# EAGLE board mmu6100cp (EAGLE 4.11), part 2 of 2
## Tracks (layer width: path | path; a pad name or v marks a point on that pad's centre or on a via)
00\  (via drill 0.61)
  Top 0.254: v64.14,104.78 v64.14,109.22
  Bottom 0.254: v64.14,104.78 87,104.78 88.9,106.68 IC12.8 | v64.14,109.22 IC16.9
00FLT\  (via drill 0.61)
  Top 0.254: v80.01,22.86 79.38,23.5 v79.38,30.48 | v69.22,30.48 67.31,32.38 v67.31,34.29 | v18.41,36.2 18.41,73.03 15.88,75.56 v15.88,87.63 | v60.96,92.08 IC16.8
  Bottom 0.254: v69.22,30.48 v79.38,30.48 | v67.31,34.29 66.04,35.56 61.59,35.56 60.96,34.92 53.34,34.92 52.7,35.56 49.53,35.56 48.9,36.2 v18.41,36.2 | v15.88,87.63 20.32,92.08 v60.96,92.08 | v80.01,22.86 IC13.3
2X\  (via drill 0.61)
  Top 0.254: v62.87,104.14 62.87,114.94 IC16.12 | v93.98,102.87 94.61,103.5 v94.61,107.95
  Bottom 0.254: v62.87,104.14 63.5,103.5 71.75,103.5 72.39,104.14 86.36,104.14 87.63,102.87 v93.98,102.87 | v94.61,107.95 95.89,109.22 IC14.6
2XFLT\  (via drill 0.61)
  Top 0.254: 124.46,6.35 101.6,6.35 97.16,10.79 97.16,13.97 93.34,17.78 93.34,19.05 90.17,19.05 88.9,17.78 IC13.5 | 124.46,6.35 124.46,22.23 123.83,22.86 v123.83,24.13 | v56.52,104.14 v56.52,111.76 | v38.1,103.5 35.56,106.05 v35.56,114.3 | v127,6.35 125.73,5.08 124.46,5.08 124.46,6.35
  Bottom 0.254: v123.83,24.13 125.09,25.4 IC18.2 | v56.52,111.76 57.15,111.76 59.69,114.3 IC16.11 | v56.52,104.14 55.88,103.5 v38.1,103.5 | v35.56,114.3 34.92,113.67 8.89,113.67 1.27,106.05 1.27,15.24 2.54,15.24 12.7,5.08 35.56,5.08 35.56,9.53 45.09,9.53 48.26,6.35 55.88,6.35 57.15,7.62 59.05,5.71 126.36,5.71 v127,6.35
AND\
  Top 0.254: IC9.15 PAD1.1
BADHLT\  (via drill 0.61)
  Top 0.254: v132.08,21.59 132.72,22.23 132.72,34.92 127,40.64 127,78.11 124.46,80.64 v124.46,88.9
  Bottom 0.254: v132.08,21.59 134.62,21.59 135.89,20.32 IC18.11 | v124.46,88.9 123.19,90.17 117.47,90.17 116.2,91.44 IC19.1
BFLD0  (via drill 0.61)
  Top 0.254: v73.03,93.98 73.03,75.56 v69.22,71.75 | v64.14,68.58 63.5,67.94 v63.5,49.53
  Bottom 0.254: IC24.7 95.25,48.26 92.71,50.8 IC4.15 90.17,50.8 88.9,52.07 74.93,52.07 72.39,49.53 v63.5,49.53 | v69.22,71.75 66.04,68.58 v64.14,68.58 | v73.03,93.98 IC23.2
BFLD1  (via drill 0.61)
  Top 0.254: IC4.12 93.34,45.09 v93.34,54.61 93.34,60.33 v93.98,60.96 | v70.48,74.93 70.48,87 IC23.4 | v85.72,74.93 87,73.66 v87,62.23
  Bottom 0.254: v93.34,54.61 94.61,55.88 IC24.4 | v85.72,74.93 v70.48,74.93 | v87,62.23 92.71,62.23 v93.98,60.96
BFLD2  (via drill 0.61)
  Top 0.254: v88.27,43.81 v88.27,55.88 88.9,56.52 88.9,62.87 88.27,63.5 88.27,82.55 v85.72,85.09
  Bottom 0.254: v88.27,43.81 85.72,43.81 85.09,43.18 IC4.9 | v88.27,55.88 89.53,57.15 93.34,57.15 94.61,58.42 IC24.3 | v85.72,85.09 71.12,85.09 69.85,83.82 IC23.6
C0\  (via drill 0.61)
  Top 0.254: v26.04,66.04 25.4,66.67 RN1.8 | v59.69,67.31 59.69,60.33 58.42,59.05 SV1.24
  Bottom 0.254: v26.04,66.04 CPU.32 38.73,66.67 43.81,66.67 44.45,67.31 v59.69,67.31
C1\  (via drill 0.61)
  Top 0.254: v57.15,69.85 57.15,62.87 58.42,61.59 SV1.22 | v27.3,69.22 27.3,94.61 27.94,95.25 RN1.9
  Bottom 0.254: v57.15,69.85 40.64,69.85 39.37,68.58 CPU.33 27.94,68.58 v27.3,69.22
C2\  (via drill 0.61)
  Top 0.254: v30.48,71.12 RN1.10 | v43.18,64.77 42.55,65.41 v42.55,71.12
  Bottom 0.254: v30.48,71.12 CPU.34 v42.55,71.12 | v43.18,64.77 56.52,64.77 57.78,63.5 SV1.20
CLRST\  (via drill 0.61)
  Top 0.254: v93.98,96.52 93.34,95.89 v93.34,64.77 | v121.28,95.25 121.28,97.79 120.02,99.06 120.02,113.03 123.19,113.03 127,116.84 IC15.3
  Bottom 0.254: IC4.1 85.09,63.5 86.36,64.77 v93.34,64.77 96.52,64.77 97.79,63.5 IC24.1 | v93.98,96.52 IC5.1 101.6,96.52 102.87,95.25 107.95,95.25 108.58,94.61 112.39,94.61 113.67,95.89 120.65,95.89 v121.28,95.25
CPREQ\  (via drill 0.61)
  Top 0.254: CPU.5 20.32,78.74 RN1.6 13.97,102.87 1.27,102.87 1.27,13.97 3.81,11.43 v12.7,11.43 | IC13.4 81.92,22.23 81.92,23.5 IC13.2 | IC13.6 89.53,15.24 89.53,14.61 IC13.8 90.17,12.7 90.17,6.99 67.94,6.99 v63.5,11.43 63.5,38.73 59.05,43.18 SV1.36 | v80.01,17.78 v80.01,20.32
  Bottom 0.254: v80.01,17.78 82.55,15.24 IC13.6 | v80.01,20.32 IC13.4 | v12.7,11.43 13.34,10.79 27.94,10.79 28.57,11.43 v63.5,11.43
CPSEL  (via drill 0.61)
  Top 0.254: IC29.9 74.3,111.12 74.3,114.94 IC29.12 | v136.53,72.39 136.53,75.56 IC22.8 | v83.82,71.12 81.28,73.66 v81.28,109.22 | v102.23,118.11 v102.23,114.3
  Bottom 0.254: v136.53,72.39 134.62,70.48 84.45,70.48 v83.82,71.12 | v81.28,109.22 IC29.9 | v102.23,118.11 78.74,118.11 77.47,116.84 IC29.12 | v102.23,114.3 IC14.11
CPSEL\  (via drill 0.61)
  Top 0.254: v3.81,64.14 2.54,62.87 v2.54,13.97 | v52.7,3.81 54.61,1.91 56.52,1.91 56.52,5.71 55.88,6.35 55.88,19.68 v56.52,20.32 | v95.89,20.32 95.89,34.92 95.25,35.56 v95.25,36.2 | v122.56,36.2 124.46,38.1 v124.46,62.23 | v131.44,62.23 132.08,62.87 v132.08,78.74
  Bottom 0.254: v3.81,64.14 5.08,64.14 20.95,80.01 24.13,80.01 25.4,81.28 CPU.38 | v2.54,13.97 12.06,4.45 44.45,4.45 45.09,3.81 v52.7,3.81 | v56.52,20.32 58.42,20.32 59.69,19.05 94.61,19.05 v95.89,20.32 | v95.25,36.2 95.89,36.83 98.42,36.83 99.69,35.56 119.38,35.56 120.02,36.2 v122.56,36.2 | v124.46,62.23 v131.44,62.23 | v132.08,78.74 IC22.9
CPUDEVSEL\  (via drill 0.61)
  Top 0.254: IC16.13 59.05,117.47 59.05,113.67 IC16.10 59.05,109.86 v59.05,98.42 | CPU.30 40.01,62.87 40.01,120.02 IC11.1 | v127.64,35.56 127.64,22.23 IC18.4 | v156.84,39.37 157.48,40.01 157.48,64.77 158.75,66.04 158.75,93.98 146.69,106.05 | 146.69,106.05 v140.34,112.39 | v117.47,118.11 116.2,119.38 116.2,120.02 115.57,120.65 107.31,120.65 107.31,120.02 IC14.13 | v108.58,98.42 112.39,94.61 113.67,94.61 v113.67,100.97 | v141.6,100.97 146.69,106.05
  Bottom 0.254: IC16.13 55.88,119.38 54.61,120.65 42.55,120.65 41.27,121.92 IC11.1 | v127.64,35.56 128.91,36.83 145.41,36.83 147.96,39.37 v156.84,39.37 | v140.34,112.39 137.16,115.57 127,115.57 124.46,118.11 v117.47,118.11 | v59.05,98.42 v108.58,98.42 | v113.67,100.97 v141.6,100.97
CPUINTREQ\  (via drill 0.61)
  Top 0.254: v12.7,70.48 RN1.3
  Bottom 0.254: v12.7,70.48 19.68,70.48 21.59,68.58 CPU.8 | IC16.3 52.07,116.84 51.44,116.2 47.62,116.2 46.99,115.57 41.91,115.57 39.37,113.03 18.41,113.03 5.08,99.69 5.08,98.42 10.79,98.42 RN1.3
CPUSWSEL\  (via drill 0.61)
  Top 0.254: v36.83,100.97 36.83,95.25 36.2,94.61 36.2,65.41 CPU.31 | v43.18,102.23 v45.72,99.69 | v82.55,102.23 81.92,102.87 81.92,107.31 82.55,107.95 85.09,107.95 86.36,109.22 86.36,114.3 87.63,115.57 89.53,115.57 89.53,113.67 90.17,113.03 93.34,113.03 93.34,111.76 94.61,110.49 95.89,110.49 | 95.89,110.49 95.89,116.2 IC14.2 | v140.34,107.31 140.34,100.97 142.88,98.42 142.88,17.78 IC18.10 | 95.89,110.49 v95.89,107.95
  Bottom 0.254: v36.83,100.97 38.1,102.23 v43.18,102.23 | v45.72,99.69 46.35,100.33 56.52,100.33 57.15,100.97 67.94,100.97 69.22,102.23 73.03,102.23 73.66,102.87 81.92,102.87 v82.55,102.23 | v140.34,107.31 137.16,110.49 113.03,110.49 110.49,107.95 v95.89,107.95
DATAF  (via drill 0.61)
  Top 0.254: v48.9,86.36 49.53,87 49.53,95.89 | 49.53,95.89 49.53,110.49 IC16.4 | v141.6,60.96 140.97,61.59 v140.97,97.16 | 49.53,95.89 v48.9,95.89
  Bottom 0.254: CPU.40 v48.9,86.36 | v140.97,97.16 108.58,97.16 107.95,97.79 59.69,97.79 57.78,95.89 v48.9,95.89 | v141.6,60.96 IC17.19
DCA\
  Top 0.254: IC9.12 PAD4.1
DEVSEL\  (via drill 0.61)
  Top 0.254: v102.87,15.24 101.6,13.97 v101.6,7.62 | v59.05,8.89 59.05,18.41 59.69,19.05 62.87,19.05 62.87,33.02 v59.69,36.2 | v16.51,40.64 13.97,43.18 13.97,85.72 13.34,86.36 13.34,87 v15.88,89.53 | v74.3,92.71 73.66,92.08 v73.66,73.66
  Bottom 0.254: v102.87,15.24 104.14,16.51 127,16.51 128.27,15.24 IC18.6 | v101.6,7.62 100.97,6.99 64.14,6.99 62.23,8.89 v59.05,8.89 | v59.69,36.2 50.16,36.2 49.53,36.83 20.32,36.83 v16.51,40.64 | v15.88,89.53 19.05,92.71 60.33,92.71 60.96,93.34 66.67,93.34 67.31,92.71 v74.3,92.71 | v73.66,73.66 67.31,67.31 60.96,67.31 59.69,68.58 SV1.16
DFLD0  (via drill 0.61)
  Top 0.254: v85.09,38.73 85.72,39.37 85.72,48.9 IC4.6
  Bottom 0.254: v85.09,38.73 85.72,38.1 90.17,38.1 91.44,36.83 92.71,36.83 93.34,37.47 99.06,37.47 100.33,36.2 118.75,36.2 120.02,37.47 135.25,37.47 137.79,40.01 IC17.11
DFLD1
  Bottom 0.254: IC4.5 85.09,53.34 85.72,52.7 89.53,52.7 90.17,52.07 95.25,52.07 97.79,49.53 132.08,49.53 135.89,45.72 IC17.13
DFLD2  (via drill 0.61)
  Top 0.254: v85.72,65.41 85.72,62.87 IC4.2 | v123.19,64.77 124.46,66.04 125.73,66.04 v125.73,53.98
  Bottom 0.254: v85.72,65.41 86.36,66.04 100.33,66.04 102.23,64.14 104.78,64.14 105.41,64.77 v123.19,64.77 | v125.73,53.98 127.64,52.07 134.62,52.07 135.89,50.8 IC17.15
DMAGNT
  Bottom 0.254: CPU.3 24.13,81.28 24.77,81.92 36.2,81.92 36.83,82.55 39.37,82.55 40.64,81.28 SV1.5
DMAREQ\
  Top 0.254: CPU.4 20.95,80.64 20.95,93.34 22.86,95.25 RN1.7
  Bottom 0.254: SV1.7 40.64,78.74 39.37,77.47 25.4,77.47 24.13,78.74 CPU.4
DX0  (via drill 0.61)
  Top 0.254: IC3.7 20.95,17.14 20.95,46.35 CPU.16 | v57.15,77.47 57.15,73.03 55.88,71.75 SV1.13 | v100.97,71.75 100.97,76.83 IC5.8 | v26.67,49.53 27.94,50.8 27.94,66.67 28.57,67.31 v28.57,72.39
  Bottom 0.254: 180.34,59.69 187.96,59.69 189.23,58.42 IC21.15 | 180.34,59.69 173.99,59.69 173.35,59.05 169.54,59.05 168.91,58.42 IC28.15 | SV1.13 RN2.2 44.45,71.12 43.18,72.39 v28.57,72.39 | IC5.8 96.52,78.74 95.25,80.01 90.17,80.01 88.9,78.74 IC7.8 82.55,78.74 81.28,77.47 v57.15,77.47 | 180.34,59.69 180.34,72.39 156.21,72.39 153.67,74.93 137.16,74.93 133.35,71.12 101.6,71.12 v100.97,71.75 | v26.67,49.53 25.4,49.53 24.13,48.26 CPU.16
DX1  (via drill 0.61)
  Top 0.254: 24.77,43.81 24.77,19.68 IC3.6 | 24.77,43.81 CPU.17 | v27.3,67.31 27.3,51.44 24.77,48.9 24.77,43.81 | v53.98,85.09 53.98,71.12 55.88,69.22 SV1.15 | v133.35,72.39 v133.35,62.23 | v108.58,77.47 v108.58,72.39 | v97.16,77.47 97.16,79.38 IC5.7
  Bottom 0.254: IC21.13 173.99,60.96 172.72,59.69 166.37,59.69 165.74,60.33 154.31,60.33 153.67,60.96 IC28.13 151.13,60.96 150.5,61.59 142.24,61.59 141.6,62.23 v133.35,62.23 | IC5.7 97.16,81.28 95.89,82.55 86.36,82.55 85.09,81.28 IC7.7 82.55,81.28 81.28,82.55 61.59,82.55 59.05,85.09 v53.98,85.09 | SV1.15 RN2.3 44.45,68.58 43.18,67.31 v27.3,67.31 | v108.58,72.39 v133.35,72.39 | v97.16,77.47 v108.58,77.47
DX2  (via drill 0.61)
  Top 0.254: v27.3,43.18 27.3,27.3 v26.67,26.67 26.67,9.53 v33.02,3.17 | v34.92,64.77 31.75,61.59 v31.75,43.18 | v80.01,88.9 80.64,88.27 80.64,73.66 v73.03,66.04 | v158.75,63.5 159.38,62.87 159.38,24.13 160.66,22.86 160.66,17.78 160.02,17.14 160.02,3.17 v159.38,2.54
  Bottom 0.254: IC28.12 v158.75,63.5 165.1,63.5 166.37,64.77 172.72,64.77 173.99,63.5 IC21.12 | IC5.4 95.89,88.9 94.61,90.17 86.36,90.17 85.09,88.9 IC7.4 v80.01,88.9 | v26.67,26.67 25.4,26.67 24.13,25.4 IC3.3 | CPU.18 v27.3,43.18 v31.75,43.18 | v34.92,64.77 39.37,64.77 40.64,66.04 RN2.4 SV1.17 56.52,66.04 57.78,64.77 71.75,64.77 v73.03,66.04 | v159.38,2.54 158.75,1.91 34.29,1.91 v33.02,3.17
DX3  (via drill 0.61)
  Top 0.254: v26.04,39.37 v26.04,27.94 25.4,27.3 25.4,9.53 v31.75,3.17 | v52.07,90.17 52.7,89.53 52.7,67.31 55.88,64.14 SV1.19 | v94.61,88.9 v94.61,91.44 | v45.72,38.73 47.62,40.64 47.62,51.44 46.99,52.07 43.81,52.07 43.81,61.59 RN2.5 | v159.38,64.77 160.02,64.14 160.02,24.77 161.29,23.5 161.29,17.14 160.66,16.51 v160.66,2.54
  Bottom 0.254: 159.38,67.31 172.72,67.31 173.99,66.04 IC21.11 | 159.38,67.31 154.94,67.31 153.67,66.04 IC28.11 | v26.04,27.94 IC3.2 | CPU.19 24.77,40.64 v26.04,39.37 45.09,39.37 v45.72,38.73 | RN2.5 SV1.19 | v52.07,90.17 77.47,90.17 | 77.47,90.17 81.28,90.17 82.55,91.44 IC7.3 | v94.61,88.9 93.34,87.63 80.01,87.63 77.47,90.17 | v94.61,91.44 IC5.3 | v159.38,64.77 159.38,67.31 | v160.66,2.54 159.38,1.27 33.66,1.27 v31.75,3.17
DX4  (via drill 0.61)
  Top 0.254: v31.75,38.1 33.02,39.37 v33.02,53.34 | v109.86,101.6 109.86,114.94 IC2.2 | v105.41,101.6 104.14,100.33 104.14,60.33 v104.78,59.69 | v164.47,58.42 164.47,26.04 IC27.19 | v72.39,62.23 73.03,61.59 v73.03,58.42
  Bottom 0.254: v33.02,53.34 36.83,57.15 40.64,57.15 44.45,60.96 RN2.6 SV1.21 56.52,60.96 57.78,62.23 v72.39,62.23 | CPU.20 v31.75,38.1 | IC27.19 168.91,22.86 170.18,24.13 187.96,24.13 189.23,22.86 IC20.19 | v105.41,101.6 v109.86,101.6 | v164.47,58.42 163.19,59.69 v104.78,59.69 93.98,59.69 92.71,58.42 IC4.18 89.53,58.42 88.27,57.15 82.55,57.15 81.92,57.78 78.11,57.78 77.47,58.42 IC6.18 v73.03,58.42
DX5  (via drill 0.61)
  Top 0.254: v41.91,38.1 45.09,41.27 45.09,42.55 RN2.13 | v116.2,90.17 116.2,114.94 IC2.3 | v102.23,58.42 v102.23,65.41 v102.23,90.17 | v162.56,62.23 162.56,20.32 IC27.18 | v60.33,55.88 59.69,55.24 59.69,44.45 57.78,44.45 56.52,43.18 SV1.35 | v71.75,57.15 v73.03,55.88
  Bottom 0.254: CPU.21 v41.91,38.1 | RN2.13 SV1.35 | IC27.18 168.91,20.32 169.54,20.95 173.35,20.95 173.99,21.59 187.96,21.59 189.23,20.32 IC20.18 | v102.23,90.17 v116.2,90.17 | v102.23,58.42 100.97,57.15 94.61,57.15 93.34,55.88 IC4.17 90.17,55.88 88.9,54.61 78.74,54.61 77.47,55.88 IC6.17 v73.03,55.88 | v162.56,62.23 142.88,62.23 139.06,66.04 102.87,66.04 v102.23,65.41 | v60.33,55.88 61.59,57.15 v71.75,57.15
DX6  (via drill 0.61)
  Top 0.254: v62.23,44.45 60.33,44.45 v60.33,43.81 | IC6.14 74.93,48.26 73.03,46.35 v73.03,45.72 74.3,44.45 v74.3,39.37 | v165.1,105.41 187.32,83.19 187.32,20.95 IC20.17 | v82.55,38.1 82.55,29.21 81.28,27.94 v81.28,17.78 | v93.34,16.51 96.52,13.34 96.52,10.16 104.14,2.54 146.05,2.54 v146.05,17.78
  Bottom 0.254: IC6.14 77.47,48.26 78.11,47.62 81.92,47.62 82.55,46.99 88.9,46.99 90.17,48.26 IC4.14 | 57.15,44.45 57.15,45.09 55.88,45.09 SV1.33 RN2.12 | 57.15,44.45 57.15,42.55 56.52,41.91 55.24,41.91 53.98,40.64 CPU.22 | v73.03,45.72 71.75,44.45 v62.23,44.45 | v60.33,43.81 59.69,44.45 57.15,44.45 | v165.1,105.41 119.38,105.41 115.57,109.22 IC2.6 | IC20.17 189.23,17.78 187.96,19.05 173.99,19.05 173.35,18.41 169.54,18.41 168.91,17.78 IC27.17 166.37,17.78 165.1,19.05 147.32,19.05 v146.05,17.78 | v74.3,39.37 75.56,38.1 v82.55,38.1 | v81.28,17.78 82.55,16.51 v93.34,16.51
DX7  (via drill 0.61)
  Top 0.254: v41.91,43.18 43.81,45.09 43.81,46.35 RN2.11 | v102.23,106.05 101.6,105.41 101.6,92.08 103.5,90.17 v103.5,48.26 | v196.85,90.17 196.85,21.59 IC20.16 | v112.39,101.6 112.39,104.78 IC2.7 | v57.15,52.07 57.15,50.16 55.88,48.9 SV1.31 | v73.03,52.07 74.3,50.8 74.3,50.16 74.93,49.53 78.11,49.53 78.11,47.62 IC6.13
  Bottom 0.254: v41.91,43.18 CPU.23 | SV1.31 RN2.11 | IC27.16 168.91,15.24 169.54,15.88 173.35,15.88 173.99,16.51 187.96,16.51 189.23,15.24 IC20.16 | IC6.13 77.47,45.72 78.74,44.45 87.63,44.45 88.9,45.72 IC4.13 92.71,45.72 93.98,46.99 102.23,46.99 v103.5,48.26 | v102.23,106.05 102.87,105.41 111.76,105.41 113.03,106.68 IC2.7 | v196.85,90.17 185.42,101.6 142.24,101.6 141.6,102.23 113.03,102.23 v112.39,101.6 | v73.03,52.07 v57.15,52.07
DX8  (via drill 0.61)
  Top 0.254: v34.29,45.72 34.92,45.09 34.92,18.41 IC1.7 | v41.91,48.26 44.45,50.8 RN2.10 | v118.11,12.06 117.47,12.7 v117.47,13.97 | v109.22,13.97 104.14,13.97 v104.14,22.86 | v86.36,22.86 85.09,24.13 85.72,24.77 85.72,36.2 81.92,40.01 81.92,43.81 IC4.8
  Bottom 0.254: 179.07,12.7 177.8,12.7 176.53,11.43 170.18,11.43 168.91,12.7 IC27.15 | 179.07,12.7 IC20.15 | IC4.8 82.55,45.72 81.28,46.99 71.12,46.99 69.85,45.72 IC6.8 60.96,45.72 59.69,46.99 40.64,46.99 | RN2.10 SV1.29 | v34.29,45.72 CPU.24 39.37,45.72 40.64,46.99 | 40.64,46.99 v41.91,48.26 | 179.07,12.7 179.07,9.53 120.65,9.53 v118.11,12.06 | v109.22,13.97 v117.47,13.97 | v104.14,22.86 103.5,23.5 100.97,23.5 100.33,24.13 87.63,24.13 v86.36,22.86
DX9  (via drill 0.61)
  Top 0.254: v177.16,10.79 177.16,13.34 IC20.13 | IC27.13 154.31,13.34 v154.31,11.43 v147.32,4.45 | v34.92,46.99 35.56,46.35 35.56,20.32 IC1.6 40.01,15.88 40.01,12.06 v46.99,5.08
  Bottom 0.254: v154.31,11.43 154.94,10.79 v177.16,10.79 | IC4.7 82.55,48.26 81.28,49.53 74.93,49.53 74.3,48.9 70.48,48.9 69.85,48.26 IC6.7 60.33,48.26 59.05,49.53 40.64,49.53 | v34.92,46.99 36.2,48.26 CPU.25 39.37,48.26 40.64,49.53 | 40.64,49.53 44.45,53.34 RN2.9 SV1.27 | v147.32,4.45 146.69,5.08 131.44,5.08 130.18,3.81 57.15,3.81 55.88,5.08 v46.99,5.08
DX10  (via drill 0.61)
  Top 0.254: IC1.3 36.2,27.3 36.2,51.44 CPU.27 | v146.05,26.67 146.05,24.13 IC27.12 | v80.01,31.75 79.38,32.38 79.38,59.69 80.64,60.96 81.92,60.96 81.92,57.78 IC4.4
  Bottom 0.254: IC27.12 165.1,17.78 166.37,16.51 172.72,16.51 173.99,17.78 IC20.12 | IC4.4 82.55,55.88 81.28,57.15 73.03,57.15 71.75,55.88 IC6.4 67.31,55.88 66.67,55.24 60.96,55.24 60.33,54.61 57.78,54.61 56.52,55.88 SV1.25 RN2.8 45.09,55.24 41.27,55.24 39.37,53.34 CPU.27 | v146.05,26.67 142.24,30.48 82.55,30.48 81.28,31.75 v80.01,31.75
DX11  (via drill 0.61)
  Top 0.254: IC1.2 40.01,29.84 40.01,53.98 CPU.28 | v81.28,30.48 81.28,53.34 82.55,54.61 85.72,54.61 85.72,56.52 IC4.3
  Bottom 0.254: CPU.28 41.91,55.88 44.45,58.42 RN2.7 SV1.23 56.52,58.42 57.78,59.69 66.04,59.69 | IC20.11 173.99,20.32 172.72,19.05 166.37,19.05 165.74,19.68 154.31,19.68 153.67,20.32 IC27.11 151.13,20.32 141.6,29.84 81.92,29.84 v81.28,30.48 | 66.04,59.69 67.31,58.42 IC6.3 | 66.04,59.69 81.28,59.69 82.55,58.42 IC4.3
EMA0  (via drill 0.61)
  Top 0.254: IC28.26 169.54,84.45 169.54,42.55 IC27.26 | v71.12,91.44 70.48,92.08 v70.48,118.11 | v20.32,102.23 v36.2,118.11 | v12.7,101.6 8.89,97.79 8.89,64.14 8.26,63.5 8.26,62.23 9.53,60.96 v9.53,48.26 | v53.34,41.91 54.61,43.18 54.61,46.35 55.24,46.99 58.42,46.99 SV1.34
  Bottom 0.254: IC28.26 168.91,86.36 169.54,85.72 173.35,85.72 173.99,85.09 176.53,85.09 177.16,85.72 177.16,90.81 175.9,90.81 IC21.1 | IC27.26 168.91,40.64 169.54,40.01 173.35,40.01 173.99,39.37 176.53,39.37 177.16,40.01 177.16,45.09 175.9,45.09 IC20.1 173.99,45.72 172.72,44.45 156.21,44.45 148.59,52.07 RN3.2 143.51,52.07 139.06,47.62 | 139.06,47.62 139.06,45.09 138.43,44.45 132.08,44.45 130.81,43.18 IC17.9 128.27,43.18 127,41.91 63.5,41.91 59.69,45.72 SV1.34 | 139.06,47.62 137.79,47.62 IC17.14 | v36.2,118.11 v70.48,118.11 | v20.32,102.23 19.68,101.6 v12.7,101.6 | v9.53,48.26 15.88,41.91 v53.34,41.91 | v71.12,91.44 IC23.18
EMA1  (via drill 0.61)
  Top 0.254: v65.41,85.09 66.04,84.45 66.04,47.62 v65.41,46.99 64.77,46.35 64.77,12.7 v68.58,8.89 | 192.41,54.61 192.41,84.45 IC21.26 | 192.41,54.61 192.41,42.55 IC20.26 | 131.44,50.16 133.35,52.07 v133.35,53.34 | 131.44,50.16 IC17.7 | IC27.2 154.31,45.09 v154.31,54.61 154.31,87 IC28.2 | 192.41,54.61 v189.87,54.61 | v132.72,8.26 133.99,9.53 133.99,40.64 131.44,43.18 131.44,50.16
  Bottom 0.254: v65.41,85.09 69.85,85.09 70.48,85.72 74.3,85.72 74.93,86.36 IC23.16 | v65.41,46.99 64.77,47.62 58.42,47.62 SV1.32 | v133.35,53.34 IC17.16 142.24,53.34 143.51,54.61 RN3.3 v154.31,54.61 v189.87,54.61 | v68.58,8.89 69.22,9.53 114.94,9.53 116.2,8.26 v132.72,8.26
EMA2  (via drill 0.61)
  Top 0.254: v64.77,80.01 65.41,79.38 65.41,51.44 v64.77,50.8 | 170.18,35.56 170.81,36.2 v170.81,43.18 v170.81,78.74 | 170.18,35.56 IC27.23 | 173.35,56.52 173.35,45.09 IC20.2 | 173.35,56.52 173.35,87 IC21.2 | 173.35,56.52 v173.99,56.52 | v60.96,50.8 61.59,51.44 61.59,55.88 60.33,57.15 52.07,57.15 52.07,34.29 55.24,31.11 v55.24,3.17 | v165.1,7.62 170.18,12.7 170.18,35.56
  Bottom 0.254: v64.77,80.01 69.85,80.01 71.12,81.28 IC23.14 | v64.77,50.8 v60.96,50.8 SV1.30 | IC17.5 130.81,53.34 135.89,58.42 IC17.18 142.24,58.42 143.51,57.15 RN3.4 146.05,57.15 146.69,56.52 v173.99,56.52 | IC20.2 v170.81,43.18 | v170.81,78.74 IC28.23 | v55.24,3.17 55.88,2.54 158.12,2.54 163.19,7.62 v165.1,7.62
ERROR\  (via drill 0.61)
  Top 0.254: v84.45,31.75 84.45,28.57 IC13.1 | v106.05,31.75 109.86,27.94 v109.86,22.86
  Bottom 0.254: v84.45,31.75 85.09,31.11 105.41,31.11 v106.05,31.75 | v109.86,22.86 IC10.3
GND  (via drill 0.61)
  Top 0.254: IC27.1 151.76,46.35 151.76,57.78 IC28.14 150.5,60.33 150.5,89.53 IC28.1 | IC27.14 144.78,20.32 RN3.1 | IC17.10 127.64,42.55 127.64,43.81 IC17.8 127.64,47.62 127.64,78.11 | 125.09,102.87 126.36,104.14 126.36,104.78 IC15.7 | 125.09,102.87 123.83,102.87 123.83,109.86 IC2.12 | IC7.13 90.81,79.38 90.81,80.64 IC7.14 89.53,83.19 89.53,87 IC7.17 90.81,89.53 90.81,90.81 IC7.18 | 125.09,102.87 126.36,101.6 126.36,81.28 127.64,80.01 127.64,78.11 | 127.64,78.11 IC22.7 | IC9.8 9.53,14.61 9.53,18.41 IC9.5 6.99,20.95 6.99,22.23 IC9.4 3.81,22.86 v3.81,53.34 | QG2.7 7.62,52.7 | v28.57,10.16 28.57,18.41 IC3.12 | IC12.7 IC7.1 81.92,94.61 81.92,75.56 IC7.10 | IC13.7 82.55,12.7 82.55,8.26 74.3,8.26 69.85,12.7 IC8.7 70.48,14.61 70.48,34.92 69.22,36.2 69.22,40.01 IC6.10 66.67,42.55 66.67,61.59 IC6.1 67.94,64.14 67.94,73.03 IC23.10 66.67,75.56 66.67,76.83 | 66.67,76.83 IC23.8 | 66.67,85.09 v65.41,86.36 | 66.67,85.09 66.67,76.83 | 66.67,85.09 66.67,104.78 IC29.7 | v41.91,53.34 41.27,53.98 41.27,72.39 v42.55,73.66
  Bottom 0.254: IC18.7 130.81,12.7 132.08,11.43 149.86,11.43 151.13,12.7 IC27.14 156.21,12.7 157.48,13.97 172.72,13.97 173.99,12.7 IC20.14 | IC17.17 173.35,55.88 173.99,55.24 175.26,56.52 IC21.14 173.99,58.42 172.72,57.15 154.94,57.15 153.67,58.42 IC28.14 | IC28.27 166.37,88.9 163.83,91.44 IC28.1 | IC27.27 166.37,43.18 165.74,43.81 155.57,43.81 153.67,45.72 IC27.1 149.86,45.72 146.05,49.53 RN3.1 144.15,48.9 144.15,41.91 132.72,41.91 131.44,40.64 IC17.10 128.27,40.64 127,39.37 101.6,39.37 100.33,40.64 IC24.10 97.79,40.64 96.52,39.37 86.36,39.37 85.09,40.64 IC4.10 | IC25.7 115.57,45.72 116.84,46.99 127,46.99 128.27,45.72 IC17.8 | IC7.10 85.09,73.66 86.36,72.39 94.61,72.39 95.89,73.66 IC5.10 | 111.76,74.93 113.03,76.2 IC19.7 | 111.76,74.93 101.6,74.93 100.33,73.66 IC5.10 | 111.76,74.93 127,74.93 128.27,76.2 IC22.7 | IC7.13 92.71,78.74 93.34,78.11 94.61,78.11 IC5.10 | IC3.12 31.75,20.32 33.02,21.59 43.18,21.59 44.45,20.32 IC1.12 | v3.81,53.34 QG2.7 8.26,53.34 10.79,50.8 CPU.15 CPU.26 39.37,50.8 v41.91,53.34 | v28.57,10.16 11.43,10.16 8.89,12.7 IC9.8 | IC11.7 39.37,106.68 40.64,105.41 48.26,105.41 49.53,106.68 IC16.7 54.61,106.68 55.88,105.41 63.5,105.41 64.77,106.68 IC29.7 69.85,106.68 71.12,105.41 81.28,105.41 82.55,106.68 IC12.7 86.36,106.68 87.63,107.95 92.71,107.95 93.98,106.68 IC14.7 | IC13.7 85.09,12.7 86.36,13.97 92.71,13.97 93.98,12.7 IC26.7 102.87,12.7 104.14,13.97 107.95,13.97 109.22,12.7 IC10.7 | IC6.10 67.31,40.64 66.67,40.01 59.69,40.01 59.05,39.37 57.78,39.37 56.52,38.1 SV1.39 | IC23.10 67.31,73.66 66.04,72.39 48.26,72.39 46.99,73.66 RN2.1 v42.55,73.66
  Bottom 0.254: v65.41,86.36 SV1.2
IFETCH  (via drill 0.61)
  Top 0.254: v41.91,77.47 43.18,78.74 v43.18,100.33 | 99.06,104.14 102.23,107.31 v102.23,110.49 | v97.79,102.87 99.06,104.14 | v97.16,115.57 97.16,106.05 99.06,104.14 | v139.7,26.67 139.7,88.9 138.43,90.17 131.44,90.17 131.44,111.12 IC15.4
  Bottom 0.254: IC26.3 100.33,22.86 101.6,21.59 111.76,21.59 113.03,20.32 IC10.4 115.57,20.32 116.84,21.59 130.81,21.59 135.89,26.67 v139.7,26.67 | v41.91,77.47 40.64,77.47 39.37,76.2 CPU.36 | v43.18,100.33 43.81,100.97 55.88,100.97 57.78,102.87 72.39,102.87 73.03,103.5 85.72,103.5 87,102.23 93.34,102.23 93.98,101.6 96.52,101.6 v97.79,102.87 | v102.23,110.49 103.5,111.76 IC14.10 | v97.16,115.57 125.73,115.57 127,114.3 IC15.4
IFLD0
  Bottom 0.254: IC24.6 104.14,50.8 105.41,52.07 126.36,52.07 127.64,50.8 IC17.6
IFLD1
  Bottom 0.254: IC24.5 100.33,53.34 101.6,54.61 125.09,54.61 126.36,55.88 IC17.4
IFLD2
  Bottom 0.254: IC24.2 100.33,60.96 100.97,61.59 104.78,61.59 105.41,62.23 123.19,62.23 124.46,60.96 IC17.2
INHIBIT  (via drill 0.61)
  Top 0.254: v87,58.42 86.36,57.78 v86.36,24.13 | v48.9,27.94 48.9,33.66 50.16,34.92 50.16,53.34 48.9,54.61 48.9,74.3 47.62,75.56 47.62,113.67 IC16.2
  Bottom 0.254: v87,58.42 87.63,58.42 90.17,60.96 IC4.19 | v86.36,24.13 78.74,24.13 77.47,25.4 IC8.13 IC8.2 67.31,25.4 66.04,26.67 50.16,26.67 v48.9,27.94
INTCLR\  (via drill 0.61)
  Top 0.254: v140.97,19.05 140.97,60.33 140.34,60.96 140.34,96.52 139.06,97.79 v139.06,116.2
  Bottom 0.254: v140.97,19.05 124.46,19.05 123.19,20.32 IC10.11 | v139.06,116.2 137.16,118.11 130.81,118.11 129.54,119.38 IC15.2
INTGNT  (via drill 0.61)
  Top 0.254: v125.09,22.86 125.73,22.23 v125.73,6.99 | v46.99,8.89 43.81,12.06 v43.81,33.66 | v15.88,34.92 11.43,39.37 v11.43,72.39
  Bottom 0.254: SV1.6 57.78,81.28 56.52,82.55 40.64,82.55 39.37,83.82 CPU.39 36.83,83.82 35.56,82.55 21.59,82.55 v11.43,72.39 | v125.73,6.99 125.09,6.35 59.69,6.35 57.15,8.89 v46.99,8.89 | v43.81,33.66 42.55,34.92 v15.88,34.92 | v125.09,22.86 IC10.12
INTREQ\  (via drill 0.61)
  Top 0.254: v78.11,31.75 78.11,16.51 88.9,16.51 90.17,17.78 IC13.10 | v19.68,32.38 19.68,93.98 v19.05,94.61 | SV1.8 58.42,79.38 57.15,80.64 v57.15,97.79 58.42,99.06 v58.42,120.65
  Bottom 0.254: v78.11,31.75 77.47,32.38 41.91,32.38 41.27,33.02 20.32,33.02 v19.68,32.38 | v19.05,94.61 43.18,94.61 46.35,97.79 v57.15,97.79 | v58.42,120.65 55.88,120.65 54.61,121.92 IC16.1
IOT\
  Top 0.254: IC9.9 PAD7.1
IR0  (via drill 0.61)
  Top 0.254: v19.68,12.06 19.68,10.79 14.61,10.79 13.34,12.06 13.34,20.95 8.89,25.4 IC9.3
  Bottom 0.254: v19.68,12.06 20.32,11.43 27.3,11.43 28.57,12.7 IC3.9
IR1
  Bottom 0.254: IC9.2 13.34,22.23 13.34,16.51 27.94,16.51 29.21,15.24 IC3.10
IR2
  Bottom 0.254: IC9.1 8.89,30.48 10.16,29.21 16.51,29.21 17.14,29.84 20.95,29.84 21.59,29.21 27.94,29.21 29.21,27.94 IC3.15
IR3\  (via drill 0.61)
  Top 0.254: v41.27,31.75 40.64,32.38 40.64,119.38 46.35,125.09 86.36,125.09 86.36,121.92 IC12.12 | v94.61,116.84 v94.61,111.76
  Bottom 0.254: v41.27,31.75 25.4,31.75 24.13,30.48 IC3.1 | v94.61,111.76 IC14.5 | IC12.12 v94.61,116.84
IR4  (via drill 0.61)
  Top 0.254: v100.97,120.65 100.97,116.2 IC14.4
  Bottom 0.254: v100.97,120.65 119.38,120.65 120.65,121.92 IC2.16
IR4\  (via drill 0.61)
  Top 0.254: v93.34,123.19 93.34,116.2 IC12.11 | v102.23,123.19 113.67,123.19 113.67,122.56 IC2.1
  Bottom 0.254: v93.34,123.19 v102.23,123.19
IR5\  (via drill 0.61)
  Top 0.254: v85.72,115.57 85.72,111.12 IC12.6
  Bottom 0.254: v85.72,115.57 95.89,115.57 97.16,116.84 IC14.3 102.23,116.84 103.5,118.11 115.57,118.11 116.84,116.84 IC2.14
IR6\  (via drill 0.61)
  Top 0.254: v88.9,111.76 89.53,111.12 v89.53,105.41 | v117.47,105.41 v117.47,108.58
  Bottom 0.254: v89.53,105.41 90.17,104.78 112.39,104.78 113.03,105.41 v117.47,105.41 | v117.47,108.58 118.11,109.22 IC2.11 | v88.9,111.76 IC12.5
IR7\  (via drill 0.61)
  Top 0.254: v87.63,104.14 v87.63,114.3
  Bottom 0.254: v87.63,114.3 IC12.4 | v87.63,104.14 IC2.8
IR8\  (via drill 0.61)
  Top 0.254: v8.26,104.14 29.21,125.09 43.81,125.09 v43.81,123.83 | v62.87,123.83 73.66,123.83 74.3,124.46 85.72,124.46 85.72,118.75 IC12.3
  Bottom 0.254: v8.26,104.14 1.91,104.14 1.91,20.95 6.35,16.51 8.89,16.51 11.43,13.97 16.51,13.97 17.14,14.61 18.41,14.61 19.05,13.97 35.56,13.97 36.83,12.7 IC1.8 | v43.81,123.83 v62.87,123.83
IR9  (via drill 0.61)
  Top 0.254: v71.75,16.51 v71.75,20.32
  Bottom 0.254: v71.75,16.51 48.26,16.51 46.99,15.24 IC1.10 | v71.75,20.32 IC8.11
IR10  (via drill 0.61)
  Top 0.254: v73.03,29.21 v73.03,17.78
  Bottom 0.254: v73.03,29.21 48.26,29.21 46.99,27.94 IC1.15 | v73.03,17.78 IC8.10
IR11  (via drill 0.61)
  Top 0.254: v47.62,13.97 47.62,28.57 IC1.16
  Bottom 0.254: v47.62,13.97 73.66,13.97 74.93,15.24 IC8.9
ISZ\
  Top 0.254: IC9.13 PAD3.1
JMP\  (via drill 0.61)
  Top 0.254: v12.06,15.88 10.16,17.78 10.16,22.86 8.89,24.13 5.08,24.13 v5.08,87.63 | v73.66,101.6 73.66,95.89 71.75,93.98 71.75,92.08 72.39,91.44 72.39,80.64 v71.75,80.01 | v85.72,80.01 87.63,78.11 87.63,62.87 88.27,62.23 88.27,57.15 87,55.88 87,38.1 v88.27,36.83 | v93.34,36.2 93.34,20.32 v95.25,18.41 | v110.49,19.05 111.76,17.78 111.76,8.89 111.12,8.26 112.39,6.99 123.83,6.99 123.83,13.34 IC10.9
  Bottom 0.254: v12.06,15.88 13.34,15.88 13.97,15.24 IC9.10 | v5.08,87.63 10.79,93.34 43.81,93.34 47.62,97.16 56.52,97.16 57.15,96.52 58.42,97.79 57.78,98.42 57.78,100.33 68.58,100.33 69.85,101.6 v73.66,101.6 | v71.75,80.01 v85.72,80.01 | v88.27,36.83 88.9,36.2 v93.34,36.2 | v95.25,18.41 95.89,19.05 v110.49,19.05
JMP_OR_JMS  (via drill 0.61)
  Top 0.254: IC25.2 113.67,57.78 113.67,56.52 IC25.3 111.76,53.34 111.76,24.77 v111.12,24.13 | v120.02,24.13 120.02,14.61 IC10.8
  Bottom 0.254: IC8.1 69.85,27.94 71.12,26.67 96.52,26.67 97.79,25.4 IC26.2 100.33,25.4 101.6,24.13 v111.12,24.13 v120.02,24.13
JMP_OR_JMS\  (via drill 0.61)
  Top 0.254: v117.47,60.96 118.75,62.23 v118.75,78.74
  Bottom 0.254: IC25.1 v117.47,60.96 | v118.75,78.74 IC19.9
JMPFLT
  Top 0.254: IC8.4 67.94,20.95 67.94,22.23 IC8.3
  Bottom 0.254: IC8.3 IC8.12
JMS\  (via drill 0.61)
  Top 0.254: v94.61,13.97 94.61,1.27 31.75,1.27 IC9.11 | v102.87,13.97 105.41,11.43 110.49,11.43 v110.49,17.78
  Bottom 0.254: v94.61,13.97 v102.87,13.97 | v110.49,17.78 111.76,19.05 119.38,19.05 120.65,17.78 IC10.10
LINK
  Top 0.254: PAD5.1 CPU.29
LXMAR  (via drill 0.61)
  Top 0.254: v24.77,54.61 24.77,61.59 CPU.10 | v71.75,54.61 71.75,40.64 73.66,38.73 73.66,38.1 74.3,38.1 75.56,39.37 75.56,40.01 IC6.11 | v120.02,34.92 120.02,27.3 IC10.13 | v94.61,73.66 96.52,71.75 v96.52,35.56
  Bottom 0.254: v24.77,54.61 27.3,52.07 39.37,52.07 41.91,54.61 56.52,54.61 57.78,53.34 SV1.28 60.33,53.34 61.59,54.61 v71.75,54.61 | 96.52,34.92 91.44,34.92 90.81,35.56 79.38,35.56 77.47,37.47 74.93,37.47 73.03,39.37 73.03,40.64 IC6.11 | 96.52,34.92 v120.02,34.92 | 96.52,34.92 v96.52,35.56 | v94.61,73.66 IC7.11
MA0  (via drill 0.61)
  Top 0.254: v79.38,76.2 78.74,76.83 78.74,109.22 IC29.10 | v94.61,76.83 96.52,78.74 v96.52,80.01 | v126.36,80.01 125.73,80.64 125.73,94.61 v125.09,95.25
  Bottom 0.254: v79.38,76.2 IC7.9 85.09,76.2 86.36,77.47 93.98,77.47 v94.61,76.83 | 193.04,78.11 191.13,78.11 IC21.23 | 193.04,78.11 197.49,78.11 197.49,40.01 IC20.23 | v126.36,80.01 v96.52,80.01 | v125.09,95.25 190.5,95.25 193.04,92.71 193.04,78.11
MA1  (via drill 0.61)
  Top 0.254: v163.19,86.36 163.19,80.64 165.1,78.74 165.1,76.2 IC28.21 | IC20.21 192.41,26.04 192.41,24.77 191.77,24.13 187.96,24.13 187.96,71.12 IC21.21
  Bottom 0.254: IC27.21 168.91,27.94 170.18,26.67 187.96,26.67 189.23,27.94 IC20.21 | IC28.21 168.91,73.66 170.18,74.93 187.96,74.93 189.23,73.66 IC21.21 | v163.19,86.36 157.48,86.36 156.21,85.09 90.17,85.09 88.9,83.82 IC7.6
MA2  (via drill 0.61)
  Top 0.254: v87.63,93.98 87.63,90.17 IC7.5 | v164.47,93.34 v164.47,81.28 | v180.97,80.01 v180.97,35.56
  Bottom 0.254: 180.97,34.29 187.96,34.29 189.23,35.56 IC20.24 | 180.97,34.29 170.18,34.29 168.91,35.56 IC27.24 | IC21.24 189.23,81.28 187.96,80.01 v180.97,80.01 170.18,80.01 168.91,81.28 IC28.24 v164.47,81.28 | v87.63,93.98 88.9,95.25 101.6,95.25 104.14,92.71 108.58,92.71 109.22,93.34 v164.47,93.34 | v180.97,35.56 180.97,34.29
MA3  (via drill 0.61)
  Top 0.254: v85.72,101.6 85.72,95.89 IC7.2 | v93.34,100.97 97.16,97.16 v97.16,82.55 | v108.58,82.55 112.39,86.36 112.39,92.08 v114.94,94.61
  Bottom 0.254: IC27.25 168.91,38.1 169.54,37.47 173.35,37.47 173.99,36.83 187.96,36.83 189.23,38.1 IC20.25 196.85,44.45 196.85,77.47 189.23,77.47 188.59,78.11 188.59,79.38 189.23,80.01 191.77,80.01 192.41,80.64 192.41,83.19 191.13,83.19 IC21.25 | IC28.25 168.91,83.82 169.54,83.19 173.35,83.19 173.99,82.55 187.96,82.55 189.23,83.82 IC21.25 | v85.72,101.6 92.71,101.6 v93.34,100.97 | v108.58,82.55 v97.16,82.55 | v114.94,94.61 115.57,93.98 163.83,93.98 164.47,94.61 187.32,94.61 189.23,92.71 191.77,92.71 192.41,92.08 192.41,84.45 191.13,84.45 IC21.25
MA4  (via drill 0.61)
  Top 0.254: 149.86,64.77 v149.22,65.41 | 149.86,64.77 149.86,43.18 IC27.3 | v149.22,86.36 149.86,85.72 149.86,64.77
  Bottom 0.254: IC21.3 173.99,86.36 172.72,87.63 154.94,87.63 153.67,86.36 IC28.3 v149.22,86.36 | v149.22,65.41 146.69,67.94 76.2,67.94 73.03,64.77 73.03,64.14 IC6.19 | IC20.3 173.99,40.64 172.72,41.91 154.94,41.91 153.67,40.64 IC27.3
MA5  (via drill 0.61)
  Top 0.254: v82.55,69.85 82.55,66.04 78.11,61.59 78.11,55.24 IC6.16 | v148.59,80.01 v148.59,71.12 | IC20.4 172.72,40.64 172.72,88.9 173.99,90.17 177.16,90.17 177.16,85.72 IC21.4
  Bottom 0.254: IC27.4 165.1,38.1 166.37,39.37 172.72,39.37 173.99,38.1 IC20.4 | v82.55,69.85 83.19,69.22 146.69,69.22 v148.59,71.12 | v148.59,80.01 IC28.4 156.21,83.82 157.48,85.09 172.72,85.09 173.99,83.82 IC21.4
MA6  (via drill 0.61)
  Top 0.254: v84.45,66.67 78.74,60.96 78.74,53.34 IC6.15 | v147.32,76.2 147.32,67.31 v146.69,66.67 146.69,39.37 v147.96,38.1
  Bottom 0.254: IC20.5 173.99,35.56 172.72,36.83 154.94,36.83 153.67,35.56 IC27.5 151.13,35.56 148.59,38.1 v147.96,38.1 | v84.45,66.67 85.09,67.31 146.05,67.31 v146.69,66.67 | v147.32,76.2 IC28.5 153.67,81.28 154.94,82.55 172.72,82.55 173.99,81.28 IC21.5
MA7  (via drill 0.61)
  Top 0.254: v78.11,34.29 78.11,41.27 IC6.12 | IC21.6 177.8,81.28 177.8,91.44 176.53,92.71 172.09,92.71 172.09,36.2 IC20.6
  Bottom 0.254: IC28.6 153.67,78.74 154.94,77.47 172.72,77.47 173.99,78.74 IC21.6 | v78.11,34.29 89.53,34.29 90.17,33.66 118.75,33.66 119.38,33.02 IC27.6 153.67,33.02 157.48,29.21 177.16,29.21 177.16,31.11 IC20.6
MA8  (via drill 0.61)
  Top 0.254: v70.48,36.2 70.48,41.27 IC6.9 | IC27.7 154.31,32.38 v154.31,34.29 154.94,34.92 154.94,53.34 155.57,53.98 v155.57,74.3
  Bottom 0.254: 155.57,74.93 168.91,74.93 170.18,76.2 IC21.7 | 155.57,74.93 154.94,74.93 153.67,76.2 IC28.7 | v70.48,36.2 71.12,35.56 78.11,35.56 78.74,34.92 90.17,34.92 90.81,34.29 119.38,34.29 120.02,33.66 150.5,33.66 151.13,34.29 v154.31,34.29 168.91,34.29 172.72,30.48 IC20.7 | v155.57,74.3 155.57,74.93
MA9  (via drill 0.61)
  Top 0.254: IC21.8 177.16,71.75 177.16,29.84 IC20.8 173.35,26.04 173.35,1.27 159.38,1.27 158.12,2.54 158.12,8.89 154.94,12.06 154.94,25.4 IC27.8 155.57,31.11 155.57,52.7 156.84,53.98 v156.84,71.12 | v71.75,68.58 71.75,62.87 70.48,61.59 70.48,52.7 IC6.6
  Bottom 0.254: v71.75,68.58 74.3,71.12 82.55,71.12 83.82,69.85 146.05,69.85 149.86,73.66 IC28.8 153.67,73.66 155.57,71.75 156.21,71.75 v156.84,71.12
MA10  (via drill 0.61)
  Top 0.254: v73.03,53.34 74.3,54.61 v74.3,64.77 | IC27.9 149.22,28.57 149.22,62.87 v148.59,63.5 147.96,64.14 147.96,66.04 148.59,66.67 v148.59,69.85 | v178.44,67.94 177.8,67.31 177.8,27.94 IC20.9
  Bottom 0.254: v74.3,64.77 74.93,65.41 84.45,65.41 85.72,66.67 145.41,66.67 v148.59,63.5 | IC6.5 v73.03,53.34 | v148.59,69.85 149.86,69.85 151.13,71.12 IC28.9 | IC20.9 173.99,25.4 173.35,26.04 169.54,26.04 168.91,26.67 154.94,26.67 153.67,25.4 IC27.9 | v178.44,67.94 IC21.9
MA11  (via drill 0.61)
  Top 0.254: v70.48,66.04 70.48,62.87 IC6.2 | v179.07,64.77 179.07,26.67 IC20.10
  Bottom 0.254: IC27.10 153.67,22.86 154.94,21.59 172.72,21.59 173.99,22.86 IC20.10 | v70.48,66.04 73.03,68.58 IC28.10 153.67,68.58 154.94,69.85 172.72,69.85 173.99,68.58 IC21.10 v179.07,64.77
MEMFETCH\  (via drill 0.61)
  Top 0.254: v117.47,15.24 v117.47,53.34 | IC25.12 121.28,55.24 121.28,53.98 IC25.11
  Bottom 0.254: IC10.6 v117.47,15.24 | v117.47,53.34 IC25.11
MEMSEL  (via drill 0.61)
  Top 0.254: IC29.4 66.67,116.2 66.67,120.02 IC29.1 62.87,121.92 62.87,122.56 62.23,123.19 57.15,123.19 57.15,112.39 57.78,111.76 57.78,104.14 v56.52,102.87 | 112.39,19.68 112.39,51.44 IC25.4 | 112.39,19.68 IC10.5 | v46.35,102.23 46.99,101.6 46.99,74.93 48.26,73.66 48.26,53.98 49.53,52.7 49.53,35.56 v48.9,34.92 | v66.04,34.29 65.41,33.66 65.41,13.34 v70.48,8.26 | v112.39,8.26 112.39,19.68
  Bottom 0.254: v56.52,102.87 55.88,102.23 v46.35,102.23 | v48.9,34.92 52.07,34.92 52.7,34.29 v66.04,34.29 | v70.48,8.26 71.12,8.89 111.76,8.89 v112.39,8.26
MEMSEL\  (via drill 0.61)
  Top 0.254: IC25.5 113.67,50.16 113.67,48.9 IC25.6 116.2,46.35 116.2,33.02 v115.57,32.38 | IC20.20 188.59,27.3 188.59,69.22 IC21.20 | v34.92,78.74 34.29,78.11 34.29,65.41 31.11,62.23 31.11,43.81 30.48,43.18 30.48,33.02 34.29,29.21 34.29,13.97 v41.91,6.35 | v122.56,31.75 127,27.3 127,7.62 128.27,6.35 v128.27,5.08
  Bottom 0.254: v41.91,6.35 46.99,6.35 47.62,5.71 56.52,5.71 57.78,4.45 128.27,4.45 | 128.27,4.45 129.54,4.45 130.81,5.71 160.02,5.71 163.19,8.89 189.23,8.89 192.41,12.06 192.41,24.77 191.13,24.77 IC20.20 | v34.92,78.74 CPU.37 | v115.57,32.38 116.2,31.75 v122.56,31.75 | 128.27,4.45 v128.27,5.08
N$2
  Top 0.254: QG1.1 QG2.1
N$3  (via drill 0.61)
  Top 0.254: v125.73,114.3 125.73,111.76 IC15.6 | v111.12,101.6 111.12,111.12 IC2.4 | v92.08,100.33 88.9,97.16 88.9,64.14 89.53,63.5 v89.53,33.02 | v94.61,28.57 v94.61,32.38 | v71.75,38.73 v71.75,27.94 | v62.23,38.73 59.05,41.91 54.61,41.91 54.61,33.02 v56.52,31.11
  Bottom 0.254: IC2.4 IC2.13 v125.73,114.3 | IC3.4 IC3.13 IC1.4 | IC1.4 IC1.13 | v111.12,101.6 109.86,100.33 93.98,100.33 93.34,99.69 92.71,99.69 v92.08,100.33 | v89.53,33.02 90.17,32.38 v94.61,32.38 | v94.61,28.57 93.98,29.21 74.3,29.21 73.03,27.94 v71.75,27.94 | v62.23,38.73 v71.75,38.73 | v56.52,31.11 55.88,31.75 49.53,31.75 46.99,29.21 44.45,29.21 IC1.4
N$5  (via drill 0.61)
  Top 0.254: v95.25,43.18 95.25,40.64 92.08,37.47 92.08,34.29 89.53,31.75 89.53,22.23 IC13.11 | v108.58,46.99 109.86,48.26 109.86,78.11 v109.22,78.74
  Bottom 0.254: v95.25,43.18 96.52,44.45 102.87,44.45 105.41,46.99 v108.58,46.99 | v109.22,78.74 110.49,77.47 125.73,77.47 127,78.74 IC22.6
N$6  (via drill 0.61)
  Top 0.254: v73.03,115.57 73.66,114.94 73.66,109.22 74.93,107.95 78.11,107.95 v78.11,72.39 | v95.25,54.61 v95.25,71.75 | v100.97,52.07 102.23,50.8 102.23,46.99 v104.78,44.45 | v122.56,43.81 123.83,45.09 123.83,56.52 IC25.13
  Bottom 0.254: v73.03,115.57 48.26,115.57 46.99,114.3 IC11.11 | v78.11,72.39 85.09,72.39 85.72,71.75 v95.25,71.75 | v95.25,54.61 97.79,52.07 v100.97,52.07 | v104.78,44.45 109.22,44.45 109.86,43.81 v122.56,43.81
N$7  (via drill 0.61)
  Top 0.254: v94.61,25.4 94.61,20.32 97.16,17.78 97.16,17.14 97.79,16.51 102.87,16.51 102.87,25.4 104.78,27.3 104.78,34.92 111.12,41.27 111.12,78.11 113.03,80.01 115.57,80.01 116.2,80.64 116.2,84.45 IC19.3
  Bottom 0.254: v94.61,25.4 IC13.13
N$8  (via drill 0.61)
  Top 0.254: v50.16,22.86 50.16,33.66 50.8,34.29 50.8,59.05 49.53,60.33 49.53,85.09 50.16,85.72 50.16,106.05 IC16.6 | v97.16,21.59 97.16,34.29 v100.33,37.47 | v106.68,38.1 110.49,41.91 110.49,78.74 113.03,81.28 IC19.5
  Bottom 0.254: v50.16,22.86 51.44,21.59 v97.16,21.59 | v100.33,37.47 100.97,38.1 v106.68,38.1
N$9  (via drill 0.61)
  Top 0.254: IC27.20 165.74,27.3 165.74,69.22 IC28.20 | v74.3,95.25 74.3,97.16 74.93,97.79 74.93,105.41 IC29.8 | v45.72,93.98 43.81,92.08 43.81,65.41 44.45,64.77 47.62,64.77 47.62,53.34 48.9,52.07 48.9,39.37 v48.26,38.73 | v73.03,37.47 74.3,36.2 74.3,14.61 74.93,13.97 88.9,13.97 v88.9,12.7 | v156.21,13.97 159.38,17.14 v159.38,22.86
  Bottom 0.254: v74.3,95.25 49.53,95.25 48.26,93.98 v45.72,93.98 | v48.26,38.73 49.53,37.47 54.61,37.47 55.24,36.83 59.05,36.83 59.69,37.47 v73.03,37.47 | v88.9,12.7 90.17,11.43 116.2,11.43 118.75,13.97 v156.21,13.97 | v159.38,22.86 161.93,25.4 IC27.20
N$10  (via drill 0.61)
  Top 0.254: v112.39,63.5 112.39,76.83 IC19.6
  Bottom 0.254: v112.39,63.5 IC17.1
N$11  (via drill 0.61)
  Top 0.254: v95.25,120.65 99.06,124.46 v103.5,124.46 | 161.93,99.06 165.74,95.25 165.74,78.11 IC28.22 | v137.79,123.19 161.93,99.06 | 161.93,99.06 161.93,80.64 163.83,78.74 163.83,62.23 163.19,61.59 163.19,21.59 168.91,21.59 169.54,22.23 169.54,28.57 IC27.22
  Bottom 0.254: v95.25,120.65 74.3,120.65 74.3,116.2 IC29.11 | v103.5,124.46 104.14,125.09 126.36,125.09 128.27,123.19 v137.79,123.19
N$15
  Bottom 0.254: IC8.6 73.66,15.24 74.93,16.51 80.01,16.51 82.55,13.97 85.09,13.97 86.36,15.24 IC13.9
OE\  (via drill 0.61)
  Top 0.254: v194.31,72.39 194.31,50.8 194.94,50.16 194.94,34.92 IC20.22 | v71.75,113.03 v71.75,109.22 | v66.67,113.03 66.04,113.67 v66.04,120.65 | v74.3,123.19 v71.75,120.65 | v87.63,123.19 92.08,123.19 v92.08,123.83 | v126.36,123.83 128.27,125.73 188.59,125.73 188.59,78.11 IC21.22
  Bottom 0.254: v194.31,72.39 IC21.22 | v66.67,113.03 v71.75,113.03 | v71.75,120.65 v66.04,120.65 | v87.63,123.19 v74.3,123.19 | v92.08,123.83 92.71,124.46 102.23,124.46 103.5,123.19 104.14,123.83 v126.36,123.83 | v71.75,109.22 IC29.6
OPR\
  Top 0.254: PAD6.1 IC9.7
OSCOUT
  Top 0.254: 15.24,52.7 QG2.8
  Bottom 0.254: QG2.8 CPU.14
POPR  (via drill 0.61)
  Top 0.254: v118.75,27.94 v118.75,55.88 | v116.84,57.78 116.2,58.42 116.2,79.38 118.11,81.28 v118.11,98.42 | v111.76,98.42 108.58,101.6 108.58,114.94 IC14.12
  Bottom 0.254: v118.75,27.94 118.11,27.94 115.57,25.4 IC10.2 | v118.75,55.88 v116.84,57.78 | v118.11,98.42 v111.76,98.42
RESET\  (via drill 0.61)
  Top 0.254: v18.41,74.93 17.14,76.2 17.14,93.34 15.24,95.25 RN1.4 | v37.47,123.83 17.78,104.14 v17.78,100.33 | v128.27,124.46 IC15.1 | v53.34,99.06 53.34,87 55.24,85.09 54.61,84.45 54.61,75.56 55.88,74.3 SV1.11
  Bottom 0.254: v18.41,74.93 19.05,74.93 CPU.7 | v128.27,124.46 127,125.73 92.08,125.73 89.53,123.19 88.9,123.19 87,125.09 38.73,125.09 v37.47,123.83 | 15.88,98.42 15.24,97.79 RN1.4 | 15.88,98.42 v17.78,100.33 | v53.34,99.06 52.7,98.42 15.88,98.42
RUN  (via drill 0.61)
  Top 0.254: v24.13,100.97 24.13,95.25 24.77,94.61 24.77,85.72 CPU.2 | v86.36,107.95 86.36,102.23 87,101.6 87,94.61 v86.36,93.98 | v102.87,92.71 103.5,93.34 103.5,119.38 100.97,121.92 IC14.1 | v161.93,16.51 161.93,61.59 160.66,62.87 160.66,97.16 v139.06,118.75
  Bottom 0.254: v24.13,100.97 31.11,107.95 v86.36,107.95 | v86.36,93.98 87.63,92.71 v102.87,92.71 | v161.93,16.51 144.78,16.51 138.43,22.86 IC18.12 | v139.06,118.75 137.16,120.65 125.73,120.65 123.19,123.19 104.78,123.19 103.5,121.92 IC14.1
RUNHLT\  (via drill 0.61)
  Top 0.254: v18.41,76.2 17.78,76.83 17.78,85.09 | 17.78,85.09 RN1.5 | v88.27,22.86 87.63,23.5 v87.63,32.38 | v51.44,33.66 v51.44,76.2 51.44,84.45 v50.8,85.09 | v18.41,85.09 17.78,85.09
  Bottom 0.254: v18.41,76.2 19.05,76.2 21.59,73.66 CPU.6 | v87.63,32.38 87,33.02 52.07,33.02 v51.44,33.66 | v88.27,22.86 IC13.12 | v51.44,76.2 SV1.9 | v50.8,85.09 v18.41,85.09
SETIF  (via drill 0.61)
  Top 0.254: v101.6,40.64 101.6,20.32 IC26.5
  Bottom 0.254: v101.6,40.64 IC24.11
SETST  (via drill 0.61)
  Top 0.254: v97.79,38.73 97.16,39.37 97.16,44.45 | 97.16,44.45 v97.16,72.39 | v91.44,38.1 IC4.11 | v125.73,43.18 125.73,40.64 131.44,34.92 131.44,24.77 IC18.3 | v109.22,43.18 107.95,41.91 104.14,41.91 101.6,44.45 97.16,44.45
  Bottom 0.254: v91.44,38.1 92.08,38.73 v97.79,38.73 | v97.16,72.39 100.33,72.39 101.6,73.66 IC5.11 | v125.73,43.18 125.09,42.55 109.86,42.55 v109.22,43.18
SETZF\  (via drill 0.61)
  Top 0.254: v111.12,88.9 111.12,94.61 107.31,98.42 107.31,106.05 IC14.8 | v89.53,124.46 91.44,124.46 92.71,125.73 118.75,125.73 118.75,101.6 116.84,99.69 116.84,90.81 117.47,90.17 116.2,88.9 IC19.2
  Bottom 0.254: 34.92,120.65 34.92,117.47 IC11.4 | 34.92,120.65 41.27,120.65 42.55,119.38 IC11.13 | IC19.2 v111.12,88.9 | 34.92,120.65 34.92,125.73 88.27,125.73 v89.53,124.46
SKP\  (via drill 0.61)
  Top 0.254: v33.02,73.66 v33.02,80.01 RN1.11 | v60.96,78.74 v60.96,66.04
  Bottom 0.254: v33.02,73.66 CPU.35 | v60.96,78.74 59.69,80.01 v33.02,80.01 | v60.96,66.04 SV1.18
SWSEL\  (via drill 0.61)
  Top 0.254: v134.62,8.26 134.62,10.16 IC18.8 | v57.15,6.35 57.15,19.68 57.78,20.32 57.78,36.83 57.15,37.47 57.15,38.73 58.42,40.01 SV1.38
  Bottom 0.254: v134.62,8.26 132.72,6.35 128.27,6.35 127,5.08 58.42,5.08 v57.15,6.35
TAD\
  Top 0.254: IC9.14 PAD2.1
UB  (via drill 0.61)
  Top 0.254: v95.25,45.72 94.61,46.35 v94.61,53.34
  Bottom 0.254: v95.25,45.72 IC24.8 | v94.61,53.34 IC4.16
UIF  (via drill 0.61)
  Top 0.254: v127.64,87.63 127.64,83.19 IC22.5 | v100.97,87.63 100.97,92.08 IC5.2
  Bottom 0.254: v100.97,87.63 v127.64,87.63
USEBF
  Bottom 0.254: IC19.4 115.57,83.82 116.84,82.55 134.62,82.55 135.89,81.28 IC22.10
USEBF\  (via drill 0.61)
  Top 0.254: v69.22,99.69 69.22,97.16 IC23.1 | v118.11,99.69 120.02,97.79 120.02,83.19 120.65,82.55 123.83,82.55 123.83,78.11 IC19.8
  Bottom 0.254: v69.22,99.69 69.85,99.06 107.95,99.06 108.58,99.69 v118.11,99.69 | IC22.11 139.06,81.92 139.06,77.47 127,77.47 125.73,76.2 IC19.8
USER_MODE  (via drill 0.61)
  Top 0.254: v102.87,26.67 102.87,40.64 100.33,43.18 IC24.9 | IC22.13 135.25,87 v135.25,38.73 135.25,17.14 IC18.9 | IC10.1 v114.3,37.47
  Bottom 0.254: v102.87,26.67 111.76,26.67 113.03,27.94 IC10.1 | IC18.5 130.81,17.78 133.35,15.24 IC18.9 | v114.3,37.47 115.57,38.73 v135.25,38.73
USER_MODE\
  Top 0.254: IC18.13 139.06,27.3 139.06,84.45 IC22.12
VCC  (via drill 0.61)
  Top 0.254: v75.56,34.29 75.56,28.57 IC8.14 | v60.96,36.2 59.05,38.1 SV1.40 v58.42,19.05 | 16.51,31.75 17.14,32.38 17.14,36.2 17.78,36.83 17.78,57.78 15.24,60.33 QG1.8 QG2.14 15.24,69.22 14.61,69.85 v14.61,86.36 | 16.51,31.75 IC9.16 | v19.68,23.5 19.68,28.57 16.51,31.75 | IC11.3 37.47,117.47 37.47,118.75 IC11.2 | 43.81,114.94 43.81,113.67 IC11.10 | 43.81,114.94 IC11.12 | 43.81,114.94 43.81,120.02 IC11.14 46.35,121.28 46.35,120.65 54.61,120.65 55.24,120.02 55.24,87.63 55.88,87 SV1.1 | 80.01,121.92 IC29.14 | 80.01,121.92 IC12.1 83.19,121.28 83.19,120.02 IC12.2 | v80.01,96.52 80.01,121.92 | IC26.10 106.05,18.41 106.05,19.68 IC26.11 106.05,20.95 106.05,22.23 IC26.12 106.05,23.5 106.05,24.77 IC26.13 106.05,26.04 106.05,27.3 IC26.14 | IC10.14 121.28,28.57 121.28,45.09 IC25.8 121.28,46.35 121.28,47.62 IC25.9 120.02,50.16 120.02,59.05 IC25.14 122.56,61.59 122.56,62.87 v124.46,64.77 | v195.58,50.8 195.58,86.36 IC21.28 | IC19.12 121.28,87 121.28,88.27 IC19.13 121.28,89.53 121.28,90.81 IC19.14 | IC15.14 137.79,120.02 137.79,92.08 IC22.14 | IC24.13 106.05,46.35 106.05,47.62 IC24.14 108.58,50.16 108.58,60.33 | IC24.17 106.05,56.52 106.05,57.78 IC24.18 108.58,60.33 | 108.58,60.33 108.58,61.59 IC24.20 104.78,65.41 104.78,83.19 | IC5.13 106.05,79.38 106.05,80.64 IC5.14 104.78,83.19 | IC5.17 106.05,89.53 106.05,90.81 IC5.18 104.78,93.34 | 104.78,93.34 104.78,94.61 IC5.20 106.68,101.6 104.78,103.5 v104.78,110.49 104.78,120.02 IC14.14 | 104.78,93.34 104.78,83.19 | v95.89,90.17 95.89,91.44 95.25,92.08 95.25,97.79 93.98,97.79 92.71,96.52 IC7.20
  Bottom 0.254: v75.56,34.29 74.93,34.92 67.94,34.92 66.67,36.2 v60.96,36.2 | 35.56,19.05 25.4,19.05 24.13,20.32 IC3.5 v19.68,23.5 | 35.56,19.05 36.83,20.32 IC1.5 | IC9.6 5.71,19.68 5.71,31.75 12.7,31.75 13.97,30.48 IC9.16 | 35.56,19.05 v58.42,19.05 | SV1.1 55.24,86.36 53.98,87.63 25.4,87.63 24.13,86.36 CPU.1 v14.61,86.36 3.81,86.36 3.81,87.63 7.62,91.44 RN1.1 | IC11.14 46.99,121.92 48.26,123.19 58.42,123.19 59.69,121.92 IC16.14 62.23,121.92 63.5,123.19 73.03,123.19 74.3,121.92 IC29.14 | IC11.12 IC11.3 | 80.01,95.25 87.63,95.25 88.9,96.52 IC7.20 | 80.01,95.25 78.74,95.25 77.47,96.52 IC23.20 | IC12.1 IC12.14 | 80.01,95.25 v80.01,96.52 | IC13.14 92.71,27.94 93.34,27.3 98.42,27.3 IC26.1 IC26.14 107.95,27.94 109.22,29.21 124.46,29.21 | IC26.11 IC26.4 | 124.46,29.21 134.62,29.21 135.89,27.94 IC18.14 | 124.46,29.21 123.19,27.94 IC10.14 | v124.46,64.77 134.62,64.77 135.89,63.5 IC17.20 | IC27.28 168.91,45.72 170.18,46.99 187.96,46.99 189.23,45.72 IC20.28 v195.58,50.8 | IC21.28 189.23,91.44 187.96,92.71 170.18,92.71 168.91,91.44 IC28.28 166.37,91.44 165.74,92.08 154.31,92.08 153.67,92.71 134.62,92.71 | 134.62,92.71 135.89,91.44 IC22.14 | 134.62,92.71 124.46,92.71 123.19,91.44 IC19.14 120.65,91.44 119.38,92.71 109.86,92.71 108.58,91.44 IC5.18 102.23,91.44 100.97,90.17 v95.89,90.17 | IC6.20 77.47,63.5 78.74,62.23 85.72,62.23 87,63.5 IC4.20 92.71,63.5 93.98,62.23 104.14,62.23 105.41,63.5 IC24.20 | v104.78,110.49 111.76,110.49 113.03,111.76 IC2.5 | IC25.8 120.65,45.72 119.38,44.45 110.49,44.45 109.22,45.72 IC24.13
WAIT\  (via drill 0.61)
  Top 0.254: v10.16,67.31 RN1.2 | v53.34,44.45 53.34,54.61 56.52,54.61 57.78,55.88 SV1.26
  Bottom 0.254: 19.68,62.87 15.24,67.31 v10.16,67.31 | 19.68,62.87 21.59,60.96 CPU.11 | v53.34,44.45 14.61,44.45 6.99,52.07 3.81,52.07 2.54,53.34 2.54,62.87 19.68,62.87
WASMEM  (via drill 0.61)
  Top 0.254: v66.67,24.13 66.67,19.68 IC8.5 | v42.55,33.66 v42.55,24.13 | v15.24,33.66 6.35,42.55 v6.35,99.69
  Bottom 0.254: v42.55,24.13 v66.67,24.13 | v15.24,33.66 v42.55,33.66 | v6.35,99.69 17.14,110.49 43.18,110.49 | 43.18,110.49 44.45,109.22 IC11.9 | 43.18,110.49 100.33,110.49 101.6,109.22 IC14.9
WE\  (via drill 0.61)
  Top 0.254: v193.68,46.35 193.04,46.99 193.04,86.36 IC21.27 | v71.75,116.84 71.75,114.3 73.03,113.03 73.03,102.23 72.39,101.6 v72.39,100.33 | v90.81,100.33 92.71,102.23 93.34,102.23 93.98,101.6 v100.33,101.6 | v187.32,90.81 v175.26,102.87
  Bottom 0.254: v193.68,46.35 IC20.27 | v90.81,100.33 v72.39,100.33 | v100.33,101.6 101.6,102.87 v175.26,102.87 | v187.32,90.81 189.23,88.9 IC21.27 | v71.75,116.84 IC29.3
XTA  (via drill 0.61)
  Top 0.254: v78.11,113.03 78.11,117.47 IC29.13 | IC22.1 130.18,92.08 130.18,109.86 IC15.5 | v63.5,76.2 63.5,92.08 66.04,94.61 66.04,109.22 IC29.5
  Bottom 0.254: CPU.9 27.3,70.48 27.3,74.93 56.52,74.93 57.78,76.2 SV1.10 v63.5,76.2 | IC29.5 73.66,111.76 74.93,113.03 v78.11,113.03 125.73,113.03 127,111.76 IC15.5
XTB  (via drill 0.61)
  Top 0.254: v29.21,88.9 29.84,88.27 29.84,72.39 29.21,71.75 v29.21,64.77 28.57,64.14 28.57,27.3 27.3,26.04 27.3,10.16 v34.29,3.17 | SV1.12 58.42,74.3 59.69,75.56 59.69,87 v58.42,88.27 65.41,95.25 65.41,118.75 v64.77,119.38 | v132.72,43.18 134.62,45.09 134.62,81.28 IC22.3 | v131.44,41.91 133.35,40.01 133.35,10.16 131.44,8.26 v131.44,3.81
  Bottom 0.254: v29.21,88.9 29.84,88.27 v58.42,88.27 | v29.21,64.77 CPU.12 | v64.77,119.38 IC29.2 | v131.44,41.91 v132.72,43.18 | v131.44,3.81 130.81,3.17 56.52,3.17 55.24,4.45 54.61,4.45 52.7,2.54 34.92,2.54 v34.29,3.17
XTC  (via drill 0.61)
  Top 0.254: v31.75,89.53 v31.75,64.77 | v60.96,87.63 62.23,86.36 v62.23,71.12 62.23,49.53 64.14,47.62 64.14,12.06 v66.04,10.16 | v116.2,9.53 116.2,15.24 116.84,15.88 116.84,46.99 116.2,47.62 116.2,54.61 118.11,56.52 118.11,58.42 120.02,60.33 120.02,79.38 IC19.10
  Bottom 0.254: v31.75,89.53 32.38,88.9 57.78,88.9 58.42,89.53 59.05,89.53 v60.96,87.63 | v31.75,64.77 CPU.13 | v62.23,71.12 SV1.14 | v116.2,9.53 115.57,10.16 v66.04,10.16
XXX7\  (via drill 0.61)
  Top 0.254: v118.11,10.79 119.38,12.06 119.38,23.5 118.75,24.13 v118.75,25.4
  Bottom 0.254: v118.11,10.79 79.38,10.79 77.47,12.7 IC8.8 | v118.75,25.4 120.02,26.67 127,26.67 128.27,27.94 IC18.1
ZF
  Bottom 0.254: IC11.5 39.37,111.76 40.64,113.03 50.8,113.03 52.07,111.76 IC16.5

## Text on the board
Bottom: VRS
